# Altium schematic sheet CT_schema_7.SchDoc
size 371 x 336 mm
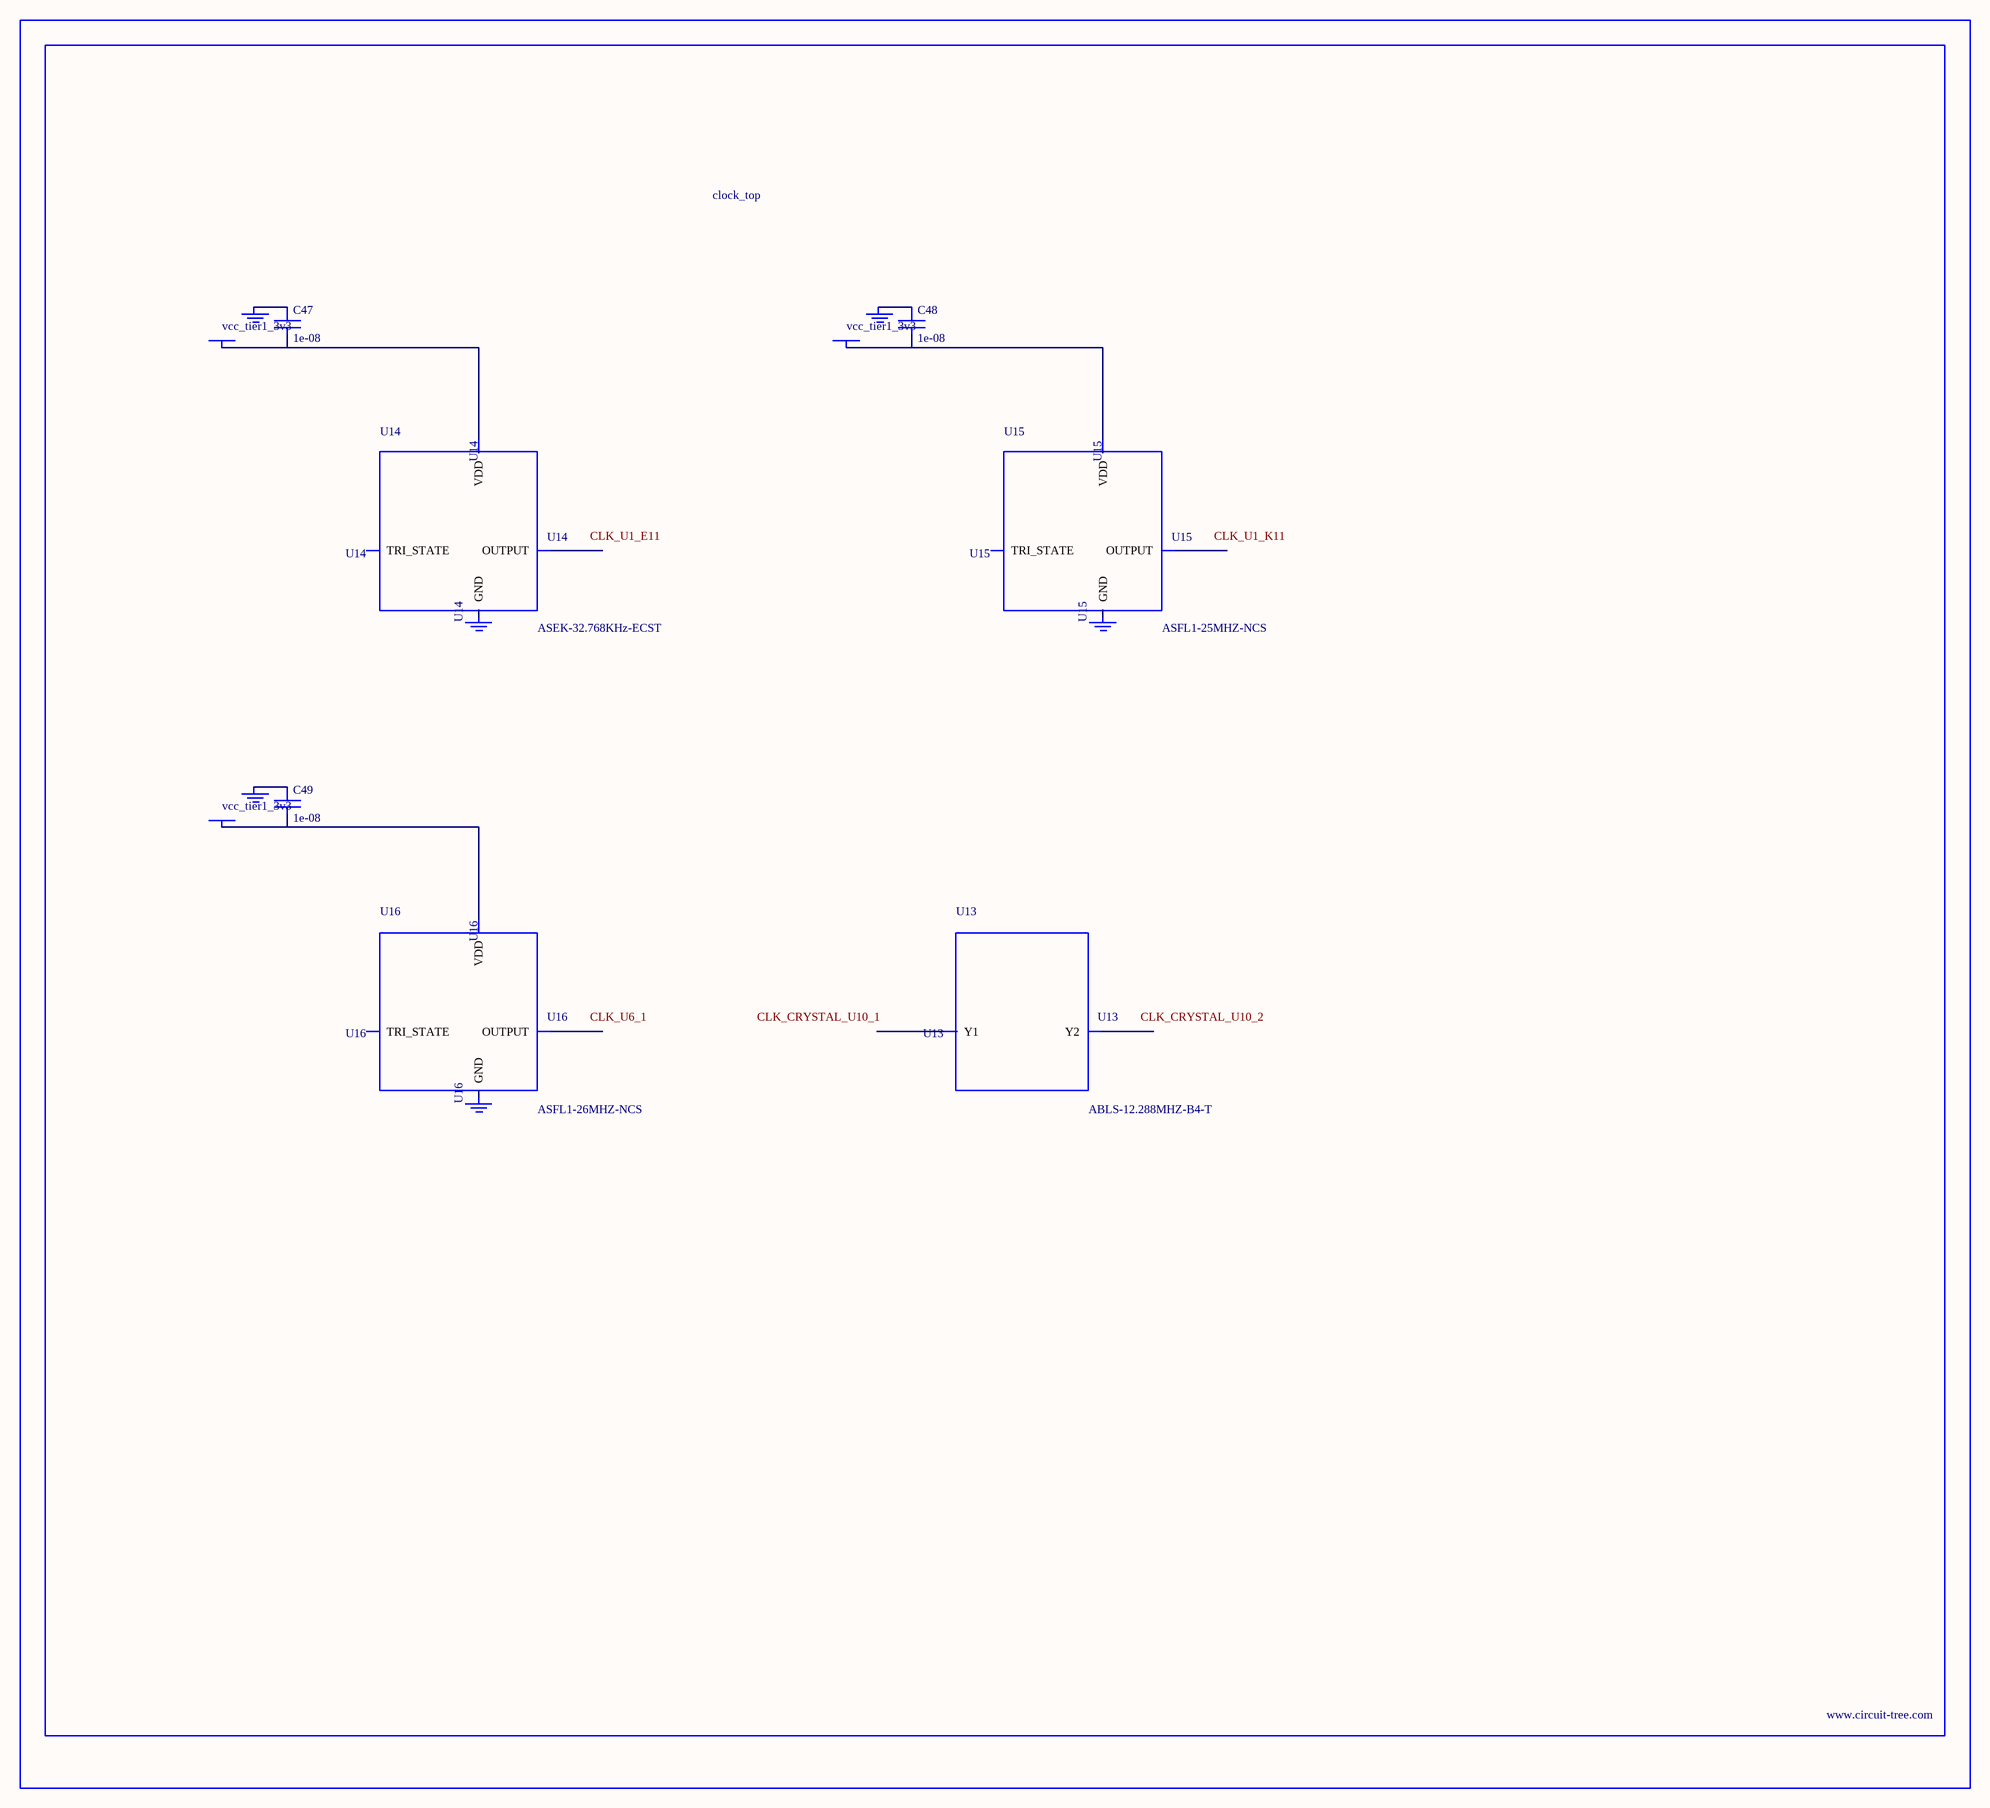
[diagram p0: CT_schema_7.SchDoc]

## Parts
BORDER6  (no value)
C47  1e-08  [C0402]
C48  1e-08  [C0402]
C49  1e-08  [C0402]
GND_INSTANCE_6_0  (no value)
GND_INSTANCE_6_1  (no value)
GND_INSTANCE_6_2  (no value)
GND_INSTANCE_6_3  (no value)
GND_INSTANCE_6_4  (no value)
GND_INSTANCE_6_5  (no value)
POWER_INSTANCE_6_0  vcc_tier1_3v3
POWER_INSTANCE_6_1  vcc_tier1_3v3
POWER_INSTANCE_6_2  vcc_tier1_3v3
U13  ABLS-12.288MHZ-B4-T  [ABLS-12.288MHZ-B4-T]
U14  ASEK-32.768KHz-ECST  [ASEK]
U15  ASFL1-25MHZ-NCS  [ASFL1]
U16  ASFL1-26MHZ-NCS  [ASFL1]

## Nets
NetC47_1: C47.1 GND_INSTANCE_6_0.0(GND)
NetC47_2: C47.2 POWER_INSTANCE_6_0.0(PWR) U14.4(VDD)
NetC48_1: C48.1 GND_INSTANCE_6_2.0(GND)
NetC48_2: C48.2 POWER_INSTANCE_6_1.0(PWR) U15.4(VDD)
NetC49_1: C49.1 GND_INSTANCE_6_4.0(GND)
NetC49_2: C49.2 POWER_INSTANCE_6_2.0(PWR) U16.4(VDD)

Not connected (* = marked no-connect by the designer): GND_INSTANCE_6_1 0(GND); GND_INSTANCE_6_3 0(GND); GND_INSTANCE_6_5 0(GND); U13 1(Y1) 2(Y2); U14 1(TRI_STATE) 2(GND) 3(OUTPUT); U15 1(TRI_STATE) 2(GND) 3(OUTPUT); U16 1(TRI_STATE) 2(GND) 3(OUTPUT)

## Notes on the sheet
- Labels drawn without touching a wire or pin: CLK_CRYSTAL_U10_1, CLK_CRYSTAL_U10_2, CLK_U1_E11, CLK_U1_K11, CLK_U6_1

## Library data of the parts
BORDER6 = BORDER_PAGE6
C47-C49 = C0402C103K3RAC
GND_INSTANCE_6_0-GND_INSTANCE_6_5 = GND
POWER_INSTANCE_6_0-POWER_INSTANCE_6_2 = PWR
